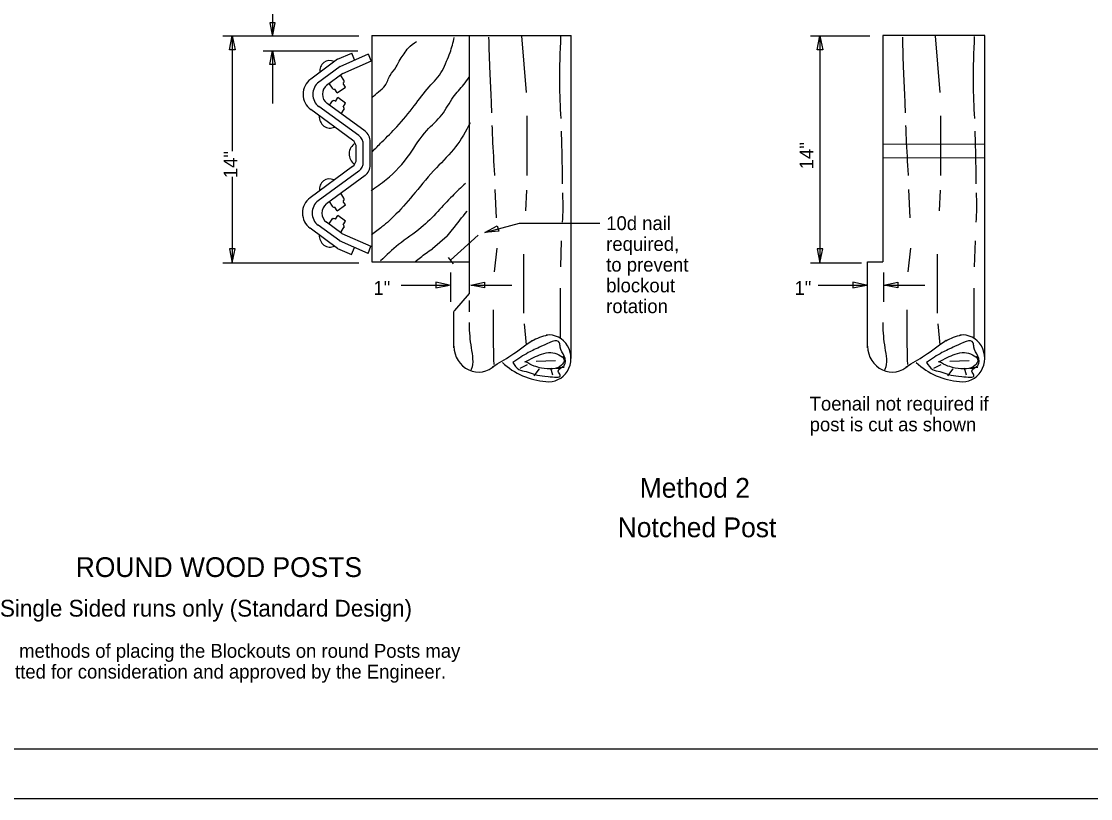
# Model space of a CAD drawing. Extents: x 0 to 34, y 0 to 22.
# Drawn here: x 8.31 to 19.13, y 0 to 7.86 of the extents above; entities that cross this region are included whole.
import ezdxf

# ---------------------------------------------------------------- set-up
doc = ezdxf.new("R2010")
doc.units = 0
for name, color, linetype in [('SH_Border', 7, 'Continuous'), ('SH_Cut_Line', 7, 'Continuous'), ('ST_Details', 7, 'Continuous'), ('ST_Text', 7, 'Continuous')]:
    doc.layers.add(name, color=color, linetype=linetype)

msp = doc.modelspace()

# ---------------------------------------------------------------- linework, layer by layer
at = {"layer": 'SH_Border'}
msp.add_lwpolyline([(1.5, 21.5), (33.5, 21.5), (33.5, 0.5), (1.5, 0.5)], close=True, dxfattribs=at)
at = {"layer": 'SH_Cut_Line'}
msp.add_lwpolyline([(0, 0), (34, 0), (34, 22), (0, 22)], close=True, dxfattribs=at)
at = {"layer": 'ST_Details'}
for p, q in [((11.853447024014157, 7.720612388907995), (11.853447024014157, 5.430445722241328)), ((11.853447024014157, 7.720612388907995), (13.87353035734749, 7.720445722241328)), ((12.839697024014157, 7.720612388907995), (12.839697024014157, 5.1087790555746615)), ((13.369697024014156, 7.7146123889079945), (13.416863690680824, 7.141945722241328)), ((13.87353035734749, 4.453612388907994), (13.87353035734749, 7.720445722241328)), ((17.026280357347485, 7.720612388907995), (17.026280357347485, 5.430445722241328)), ((18.06011369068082, 7.720445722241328), (17.026280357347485, 7.720612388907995)), ((17.556280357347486, 7.7146123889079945), (17.60344702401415, 7.141945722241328)), ((18.06011369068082, 4.453612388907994), (18.06011369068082, 7.720445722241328)), ((11.508863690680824, 7.478612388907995), (11.235947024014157, 7.278779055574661)), ((11.508613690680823, 7.4791123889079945), (11.65253035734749, 7.541779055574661)), ((11.533363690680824, 7.406112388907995), (11.82278035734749, 7.532445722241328)), ((11.68003035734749, 7.471779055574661), (11.652947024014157, 7.541112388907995)), ((11.848947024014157, 7.462112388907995), (11.821947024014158, 7.531445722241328)), ((11.535863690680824, 7.407445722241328), (11.305863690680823, 7.238945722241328)), ((11.562530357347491, 7.335445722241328), (11.852030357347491, 7.461779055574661)), ((11.561697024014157, 7.335112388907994), (11.394947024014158, 7.212945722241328)), ((11.572363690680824, 7.268279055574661), (11.542197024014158, 7.3156123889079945)), ((11.456530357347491, 7.1857790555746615), (11.427447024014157, 7.231445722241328)), ((11.505280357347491, 7.1392790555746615), (11.482113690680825, 7.175612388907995)), ((11.505113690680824, 7.139779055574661), (11.587613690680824, 7.198279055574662)), ((11.587530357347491, 7.198279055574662), (11.564863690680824, 7.2337790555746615)), ((11.426863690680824, 7.013112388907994), (11.458613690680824, 7.063112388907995)), ((11.486863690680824, 7.053445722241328), (11.51153035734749, 7.092112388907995)), ((11.59003035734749, 7.034445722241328), (11.511363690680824, 7.091945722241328)), ((11.56578035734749, 6.995945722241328), (11.589697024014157, 7.0336123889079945)), ((11.65953035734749, 6.661779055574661), (11.236280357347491, 6.970112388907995)), ((11.722697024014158, 6.706779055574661), (11.31878035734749, 7.001112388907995)), ((11.785863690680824, 6.751779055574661), (11.401197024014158, 7.032112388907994)), ((11.544947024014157, 6.927112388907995), (11.575947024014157, 6.975612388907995)), ((13.42428035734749, 6.908445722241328), (13.42428035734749, 6.303779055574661)), ((17.61086369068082, 6.908445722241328), (17.61086369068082, 6.303779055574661)), ((11.768697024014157, 6.440779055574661), (11.768697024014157, 6.614112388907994)), ((11.83953035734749, 6.411279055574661), (11.83953035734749, 6.643779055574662)), ((17.026280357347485, 6.621529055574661), (18.061197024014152, 6.6247790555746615)), ((11.697863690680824, 6.470279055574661), (11.697863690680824, 6.584612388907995)), ((11.768697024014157, 6.522112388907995), (11.768697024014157, 6.532945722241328)), ((11.659697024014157, 6.393112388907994), (11.229363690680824, 6.077612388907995)), ((17.026280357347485, 6.480695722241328), (18.060613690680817, 6.4839457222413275)), ((11.722863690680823, 6.348279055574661), (11.31178035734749, 6.046945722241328)), ((11.786113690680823, 6.303279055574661), (11.394447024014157, 6.016112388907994)), ((11.572363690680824, 6.075612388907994), (11.542197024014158, 6.122945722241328)), ((13.100697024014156, 6.161779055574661), (13.11303035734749, 5.874279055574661)), ((13.419363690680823, 6.154112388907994), (13.410197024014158, 5.944779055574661)), ((17.287280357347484, 6.161779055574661), (17.299613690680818, 5.874279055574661)), ((17.605947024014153, 6.154112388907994), (17.596780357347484, 5.944779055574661)), ((11.456530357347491, 5.992945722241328), (11.427447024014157, 6.038612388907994)), ((11.505280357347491, 5.946612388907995), (11.482113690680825, 5.982945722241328)), ((11.505113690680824, 5.946945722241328), (11.587613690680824, 6.005612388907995)), ((11.587530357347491, 6.005445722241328), (11.564863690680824, 6.040945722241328)), ((11.426863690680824, 5.8204457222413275), (11.458613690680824, 5.870445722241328)), ((11.486863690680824, 5.860779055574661), (11.51153035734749, 5.899445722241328)), ((11.59003035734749, 5.841779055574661), (11.511363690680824, 5.899279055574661)), ((11.509113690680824, 5.565279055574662), (11.229697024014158, 5.7691123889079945)), ((11.529947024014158, 5.641279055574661), (11.312113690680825, 5.799945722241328)), ((11.55203035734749, 5.716279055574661), (11.394613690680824, 5.830945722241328)), ((11.544947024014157, 5.734279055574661), (11.575947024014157, 5.782945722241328)), ((11.56578035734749, 5.803279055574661), (11.589697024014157, 5.840779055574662)), ((11.817780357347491, 5.515612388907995), (11.528363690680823, 5.641779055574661)), ((11.55203035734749, 5.716779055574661), (11.845697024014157, 5.588612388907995)), ((12.250947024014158, 5.694945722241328), (12.250947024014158, 5.694945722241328)), ((12.615780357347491, 5.689945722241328), (12.467863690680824, 5.562445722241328)), ((12.650197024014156, 5.4452790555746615), (12.930613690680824, 5.698945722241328)), ((13.772447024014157, 5.643445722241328), (13.76478035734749, 5.378279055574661)), ((17.959030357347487, 5.643445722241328), (17.951363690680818, 5.378279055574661)), ((11.506863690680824, 5.566279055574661), (11.650780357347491, 5.503445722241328)), ((11.649947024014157, 5.503779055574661), (11.678280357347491, 5.576279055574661)), ((11.816947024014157, 5.515612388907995), (11.845613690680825, 5.589112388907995)), ((13.118947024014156, 5.569279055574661), (13.093613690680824, 5.327112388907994)), ((17.305530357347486, 5.569279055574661), (17.280197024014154, 5.327112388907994)), ((11.853447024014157, 5.430445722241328), (12.84503035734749, 5.430445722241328)), ((12.68153035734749, 5.410945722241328), (12.630613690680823, 5.472112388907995)), ((13.390697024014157, 5.507112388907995), (13.390697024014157, 4.909612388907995)), ((16.871780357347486, 4.6392790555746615), (16.871780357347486, 5.430445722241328)), ((16.871780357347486, 5.430445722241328), (17.026280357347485, 5.430445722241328)), ((17.577280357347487, 5.507112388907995), (17.577280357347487, 4.909612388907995)), ((12.839697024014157, 5.1087790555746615), (12.691947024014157, 4.938112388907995)), ((12.839697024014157, 5.037612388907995), (12.839697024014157, 4.923779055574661)), ((12.685197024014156, 4.6392790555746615), (12.685197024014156, 4.9261123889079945)), ((12.691947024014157, 4.9309457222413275), (12.691947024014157, 4.938112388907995)), ((13.397863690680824, 4.803612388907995), (13.417613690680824, 4.589445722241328)), ((17.584447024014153, 4.803612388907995), (17.60419702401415, 4.589445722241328)), ((12.685197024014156, 4.560945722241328), (12.685197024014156, 4.6392790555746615)), ((16.871780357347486, 4.560945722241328), (16.871780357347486, 4.6392790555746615)), ((13.80053035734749, 4.440112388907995), (13.794613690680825, 4.474779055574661)), ((17.987113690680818, 4.440112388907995), (17.98119702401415, 4.474779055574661)), ((13.35703035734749, 4.354779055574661), (13.43103035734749, 4.390279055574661)), ((13.498113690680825, 4.276445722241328), (13.551947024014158, 4.3476123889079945)), ((13.518363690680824, 4.425779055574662), (13.713197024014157, 4.432945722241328)), ((13.68628035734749, 4.2836123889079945), (13.666113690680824, 4.354779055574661)), ((13.80128035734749, 4.361112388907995), (13.720613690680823, 4.353945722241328)), ((13.720613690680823, 4.353945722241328), (13.760197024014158, 4.354779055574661)), ((17.543613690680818, 4.354779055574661), (17.61761369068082, 4.390279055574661)), ((17.684697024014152, 4.276445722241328), (17.738530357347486, 4.3476123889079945)), ((17.704947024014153, 4.425779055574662), (17.899780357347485, 4.432945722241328)), ((17.87286369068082, 4.2836123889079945), (17.85269702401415, 4.354779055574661)), ((17.98786369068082, 4.361112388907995), (17.907197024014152, 4.353945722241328)), ((17.907197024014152, 4.353945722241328), (17.946780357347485, 4.354779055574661))]:
    msp.add_line(p, q, dxfattribs=at)
for centre, major_axis, ratio, start_param, end_param in [((11.428547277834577, 7.35975966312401), (-1.7132284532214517e-17, -0.10653593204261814), 0.9445438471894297, 2.6872111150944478, 4.851440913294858), ((11.336730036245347, 7.1245756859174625), (-3.014770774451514e-17, -0.18747144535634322), 0.9445438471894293, 3.7470844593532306, 5.680264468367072), ((11.556454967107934, 7.255854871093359), (1.2145060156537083e-18, 0.019834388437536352), 0.9445438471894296, 3.7043701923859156, 5.352473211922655), ((11.399075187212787, 7.124683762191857), (-2.4118166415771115e-17, -0.14997715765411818), 0.9445438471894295, 3.7471373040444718, 5.680323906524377), ((11.46144141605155, 7.124774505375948), (-1.8088624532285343e-17, -0.11248286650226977), 0.9445438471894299, 3.747102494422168, 5.680297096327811), ((11.469404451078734, 7.196378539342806), (-3.142739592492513e-18, -0.01954290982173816), 0.9445438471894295, 5.247458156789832, 6.879591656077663), ((11.471088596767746, 7.039917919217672), (1.2880049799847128e-18, 0.021034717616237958), 0.9445438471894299, 5.4523006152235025, 7.118325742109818), ((11.556745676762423, 6.977427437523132), (1.2880049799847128e-18, 0.021034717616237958), 0.9445438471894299, 4.196406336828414, 5.735380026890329), ((11.431739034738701, 6.897239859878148), (-1.8497404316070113e-17, -0.11502483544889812), 0.9445438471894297, 4.64065114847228, 6.714316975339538), ((11.715549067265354, 6.643707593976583), (8.035522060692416e-18, 0.13123003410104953), 0.9445438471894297, 4.71238898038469, 5.680267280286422), ((11.738150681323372, 6.521138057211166), (-1.929587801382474e-17, -0.11999008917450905), 0.9445438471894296, 3.613765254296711, 5.741419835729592), ((11.609304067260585, 6.584565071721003), (5.739657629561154e-18, 0.09373572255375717), 0.9445438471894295, 4.71238898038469, 5.68037747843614), ((11.662426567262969, 6.6141456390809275), (6.8875891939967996e-18, 0.11248286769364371), 0.9445438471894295, 4.71238898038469, 5.680339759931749), ((11.609304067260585, 6.470209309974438), (-1.5073853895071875e-17, -0.09373572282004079), 0.9445438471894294, 0.6055627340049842, 1.5707963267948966), ((11.662426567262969, 6.440778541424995), (-1.8088624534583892e-17, -0.11248286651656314), 0.9445438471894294, 0.6056505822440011, 1.5707963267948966), ((11.715549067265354, 6.411198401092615), (-2.110339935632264e-17, -0.13123003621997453), 0.9445438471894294, 0.6055663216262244, 1.5707963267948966), ((11.425525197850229, 6.162841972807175), (-1.7132284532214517e-17, -0.10653593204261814), 0.9445438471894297, 2.6872111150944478, 4.851440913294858), ((11.33010480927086, 5.923497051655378), (-3.0147707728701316e-17, -0.18747144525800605), 0.9445438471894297, 3.7470910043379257, 5.6802800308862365), ((11.556454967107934, 6.06313654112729), (1.2145060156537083e-18, 0.019834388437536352), 0.9445438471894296, 3.7043701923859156, 5.352473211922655), ((11.392427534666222, 5.923610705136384), (-2.4118166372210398e-17, -0.14997715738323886), 0.9445438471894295, 3.7471148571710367, 5.680354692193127), ((11.454839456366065, 5.923718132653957), (-1.8088624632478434e-17, -0.11248286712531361), 0.9445438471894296, 3.747102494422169, 5.680258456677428), ((11.469404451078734, 6.003660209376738), (-3.142739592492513e-18, -0.01954290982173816), 0.9445438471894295, 5.247458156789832, 6.879591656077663), ((11.471088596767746, 5.847199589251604), (1.2880049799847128e-18, 0.021034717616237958), 0.9445438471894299, 5.4523006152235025, 7.118325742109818), ((11.556745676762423, 5.7847091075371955), (1.2880049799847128e-18, 0.021034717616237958), 0.9445438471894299, 4.196406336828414, 5.735380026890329), ((11.431739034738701, 5.693923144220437), (-1.8497404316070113e-17, -0.11502483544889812), 0.9445438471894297, 4.64065114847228, 6.714316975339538), ((13.718377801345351, 4.187549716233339), (3.1110609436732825e-17, 0.5080748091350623), 0.9445438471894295, 0.17943739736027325, 0.5303528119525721), ((13.646788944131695, 4.453758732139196), (1.4492221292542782e-17, 0.23667593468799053), 0.9445438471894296, 2.997306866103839, 6.4059503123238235), ((17.90496113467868, 4.187549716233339), (3.1110609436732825e-17, 0.5080748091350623), 0.9445438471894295, 0.17943739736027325, 0.5303528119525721), ((17.833372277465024, 4.453758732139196), (1.4492221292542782e-17, 0.23667593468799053), 0.9445438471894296, 2.997306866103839, 6.4059503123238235), ((12.934531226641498, 4.578969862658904), (-4.245406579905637e-17, -0.2639976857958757), 0.9445438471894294, 4.7265868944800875, 7.018322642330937), ((17.121114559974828, 4.578969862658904), (-4.245406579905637e-17, -0.2639976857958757), 0.9445438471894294, 4.7265868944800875, 7.018322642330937), ((13.660946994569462, 4.998499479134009), (-1.254338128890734e-16, -0.7800015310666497), 0.9445438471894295, 5.5640474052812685, 6.222034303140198), ((17.847530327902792, 4.998499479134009), (-1.254338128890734e-16, -0.7800015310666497), 0.9445438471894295, 5.5640474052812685, 6.222034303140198)]:
    msp.add_ellipse(centre, major_axis=major_axis, ratio=ratio, start_param=start_param, end_param=end_param, dxfattribs=at)
for points in [[(11.858363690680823, 6.543279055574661), (11.956530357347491, 6.643279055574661), (12.109113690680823, 6.797112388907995), (12.283447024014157, 7.008612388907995), (12.43603035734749, 7.200945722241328), (12.56678035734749, 7.362445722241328), (12.610363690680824, 7.458612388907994), (12.64678035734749, 7.547112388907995), (12.689197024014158, 7.699779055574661)], [(13.037197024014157, 7.702112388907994), (13.048030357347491, 7.349445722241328), (13.061447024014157, 7.064945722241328), (13.065863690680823, 6.9374457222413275)], [(13.765113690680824, 7.7099457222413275), (13.75353035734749, 7.242779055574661), (13.765947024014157, 6.880112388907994)], [(17.223780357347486, 7.702112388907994), (17.23461369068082, 7.349445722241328), (17.248030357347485, 7.064945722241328), (17.252447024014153, 6.9374457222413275)], [(17.951697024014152, 7.7099457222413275), (17.940113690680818, 7.242779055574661), (17.952530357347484, 6.880112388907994)], [(11.85478035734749, 7.089445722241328), (11.923863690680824, 7.150945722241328), (11.989197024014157, 7.212445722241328), (12.040113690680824, 7.316279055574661), (12.101863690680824, 7.400945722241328), (12.141780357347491, 7.477945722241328), (12.18178035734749, 7.535612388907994), (12.225363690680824, 7.593279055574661), (12.30828035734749, 7.659279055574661)], [(11.847530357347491, 6.150945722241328), (12.000113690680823, 6.262445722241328), (12.239863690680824, 6.520279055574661), (12.41053035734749, 6.758612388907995), (12.563197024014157, 6.916445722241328), (12.679447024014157, 7.097112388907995), (12.784863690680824, 7.223945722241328), (12.840363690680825, 7.298279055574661)], [(12.85103035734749, 6.835445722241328), (12.70328035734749, 6.593612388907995), (12.508447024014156, 6.380112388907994), (12.293363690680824, 6.131112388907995), (12.09853035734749, 5.910779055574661), (11.957447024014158, 5.782612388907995), (11.849863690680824, 5.704279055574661)], [(13.070363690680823, 6.809445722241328), (13.074863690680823, 6.6809457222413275), (13.09503035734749, 6.310945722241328), (13.095363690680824, 6.304112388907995)], [(13.770447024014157, 6.752112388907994), (13.773613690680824, 6.659445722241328), (13.782197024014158, 6.218779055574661)], [(17.256947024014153, 6.809445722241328), (17.261447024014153, 6.6809457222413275), (17.281613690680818, 6.310945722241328), (17.28194702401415, 6.304112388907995)], [(17.957030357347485, 6.752112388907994), (17.960197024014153, 6.659445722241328), (17.968780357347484, 6.218779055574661)], [(12.804030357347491, 6.223612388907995), (12.669613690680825, 6.095612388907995), (12.52178035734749, 5.939112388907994), (12.35378035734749, 5.775612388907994), (12.125363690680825, 5.604779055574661), (11.94403035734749, 5.439612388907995)], [(13.78403035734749, 6.1264457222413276), (13.787113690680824, 5.9694457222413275), (13.78228035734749, 5.832279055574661)], [(17.970613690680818, 6.1264457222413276), (17.973697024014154, 5.9694457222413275), (17.96886369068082, 5.832279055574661)], [(12.615780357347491, 5.689945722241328), (12.672197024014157, 5.758612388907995), (12.818197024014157, 5.943279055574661)], [(12.29428035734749, 5.431612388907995), (12.40328035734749, 5.516445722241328), (12.467863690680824, 5.562445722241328)], [(13.760947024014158, 5.1647790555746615), (13.760947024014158, 4.951445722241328), (13.760947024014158, 4.702445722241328), (13.760947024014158, 4.659779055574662)], [(17.947530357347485, 5.1647790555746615), (17.947530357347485, 4.951445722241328), (17.947530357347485, 4.702445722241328), (17.947530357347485, 4.659779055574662)], [(13.081530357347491, 4.945112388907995), (13.081530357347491, 4.774445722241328), (13.088280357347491, 4.390279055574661)], [(17.268113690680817, 4.945112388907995), (17.268113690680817, 4.774445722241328), (17.274863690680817, 4.390279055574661)], [(12.839697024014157, 4.8171123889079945), (12.839697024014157, 4.795779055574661), (12.859780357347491, 4.560945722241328), (12.859780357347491, 4.340445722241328), (12.853113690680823, 4.326279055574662)], [(17.026280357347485, 4.8171123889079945), (17.026280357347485, 4.795779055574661), (17.04636369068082, 4.560945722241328), (17.04636369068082, 4.340445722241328), (17.039697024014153, 4.326279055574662)], [(13.283197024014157, 4.411612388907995), (13.437697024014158, 4.511279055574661), (13.572113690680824, 4.575279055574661), (13.75353035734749, 4.610779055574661), (13.760947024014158, 4.567279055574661), (13.80128035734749, 4.474779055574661), (13.80128035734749, 4.382445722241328), (13.740863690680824, 4.325445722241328), (13.760197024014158, 4.2836123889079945), (13.639197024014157, 4.269445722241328), (13.53178035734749, 4.2836123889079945), (13.417613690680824, 4.319112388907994), (13.343613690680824, 4.340445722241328), (13.283197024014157, 4.411612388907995)], [(17.469780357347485, 4.411612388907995), (17.624280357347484, 4.511279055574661), (17.75869702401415, 4.575279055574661), (17.940113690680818, 4.610779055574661), (17.947530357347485, 4.567279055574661), (17.98786369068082, 4.474779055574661), (17.98786369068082, 4.382445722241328), (17.927447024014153, 4.325445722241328), (17.946780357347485, 4.2836123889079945), (17.825780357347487, 4.269445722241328), (17.718363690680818, 4.2836123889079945), (17.60419702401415, 4.319112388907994), (17.530197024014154, 4.340445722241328), (17.469780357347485, 4.411612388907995)], [(13.074863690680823, 4.368945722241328), (13.262947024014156, 4.482779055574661), (13.481197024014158, 4.638945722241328)], [(17.261447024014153, 4.368945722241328), (17.449530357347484, 4.482779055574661), (17.667780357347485, 4.638945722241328)], [(13.404113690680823, 4.418779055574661), (13.491447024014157, 4.461445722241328), (13.572113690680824, 4.497112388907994), (13.666113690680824, 4.511279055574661), (13.74678035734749, 4.489945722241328), (13.80053035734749, 4.440112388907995), (13.773613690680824, 4.383112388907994), (13.68628035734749, 4.3476123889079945), (13.572113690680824, 4.354779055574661), (13.498113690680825, 4.376112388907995), (13.410780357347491, 4.418779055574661)], [(17.59069702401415, 4.418779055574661), (17.678030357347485, 4.461445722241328), (17.75869702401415, 4.497112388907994), (17.85269702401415, 4.511279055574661), (17.933363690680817, 4.489945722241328), (17.987113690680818, 4.440112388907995), (17.960197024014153, 4.383112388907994), (17.87286369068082, 4.3476123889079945), (17.75869702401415, 4.354779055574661), (17.684697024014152, 4.376112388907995), (17.59736369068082, 4.418779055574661)]]:
    msp.add_spline(points, degree=3, dxfattribs=at)
at = {"layer": 'ST_Text'}
for p, q in [((10.849113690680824, 8.36219289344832), (10.849113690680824, 7.708612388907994)), ((10.34853035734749, 7.715945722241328), (11.72278035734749, 7.715945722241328)), ((10.44303035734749, 7.715945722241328), (10.44303035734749, 6.549279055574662)), ((16.295780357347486, 7.715945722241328), (16.89561369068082, 7.715945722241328)), ((16.390280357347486, 7.715945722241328), (16.390280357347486, 6.549279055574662)), ((10.754697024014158, 7.565779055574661), (11.712197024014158, 7.565779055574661)), ((10.849113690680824, 7.565779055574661), (10.849113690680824, 7.0302790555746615)), ((16.390280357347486, 6.549279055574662), (16.390280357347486, 6.291112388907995)), ((10.44303035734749, 6.291112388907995), (10.44303035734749, 5.421445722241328)), ((16.390280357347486, 6.291112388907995), (16.390280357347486, 5.421445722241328)), ((12.997197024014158, 5.727112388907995), (13.347697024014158, 5.819779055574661)), ((13.347697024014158, 5.819779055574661), (14.161947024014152, 5.819779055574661)), ((10.34853035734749, 5.421445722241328), (11.447197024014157, 5.421445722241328)), ((11.447197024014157, 5.421445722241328), (11.72278035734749, 5.421445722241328)), ((16.295780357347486, 5.421445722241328), (16.620030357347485, 5.421445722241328)), ((16.620030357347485, 5.421445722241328), (16.809197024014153, 5.421445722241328)), ((12.649613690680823, 5.322779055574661), (12.649613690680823, 5.026112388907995)), ((17.032197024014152, 5.322779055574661), (17.032197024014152, 5.026112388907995)), ((12.15303035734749, 5.195445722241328), (12.642447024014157, 5.195445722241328)), ((12.855947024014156, 5.195445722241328), (13.27028035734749, 5.195445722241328)), ((16.37261369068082, 5.195445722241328), (16.862030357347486, 5.195445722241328)), ((17.03719702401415, 5.195445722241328), (17.451530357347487, 5.195445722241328))]:
    msp.add_line(p, q, dxfattribs=at)
for points in [[(10.821113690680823, 7.848612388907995), (10.849113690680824, 7.708612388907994), (10.877113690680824, 7.848612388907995)], [(10.41503035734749, 7.575945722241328), (10.44303035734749, 7.715945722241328), (10.471030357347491, 7.575945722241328)], [(16.362280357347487, 7.575945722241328), (16.390280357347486, 7.715945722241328), (16.418280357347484, 7.575945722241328)], [(10.821113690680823, 7.425779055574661), (10.849113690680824, 7.565779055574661), (10.877113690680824, 7.425779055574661)], [(13.139491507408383, 5.738786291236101), (12.997197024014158, 5.727112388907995), (13.124055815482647, 5.79261694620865)], [(10.41503035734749, 5.561445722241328), (10.44303035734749, 5.421445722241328), (10.471030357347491, 5.561445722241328)], [(16.362280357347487, 5.561445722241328), (16.390280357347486, 5.421445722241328), (16.418280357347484, 5.561445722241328)], [(12.502447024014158, 5.167445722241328), (12.642447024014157, 5.195445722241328), (12.502447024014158, 5.223445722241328)], [(12.995947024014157, 5.167445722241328), (12.855947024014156, 5.195445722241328), (12.995947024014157, 5.223445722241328)], [(16.722030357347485, 5.167445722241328), (16.862030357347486, 5.195445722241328), (16.722030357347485, 5.223445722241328)], [(17.177197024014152, 5.167445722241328), (17.03719702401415, 5.195445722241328), (17.177197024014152, 5.223445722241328)]]:
    msp.add_lwpolyline(points, close=True, dxfattribs=at)

# ---------------------------------------------------------------- texts
for p in [(16.323268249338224, 6.366505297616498), (10.494087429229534, 6.276050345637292)]:
    msp.add_text('14" ', height=0.13999972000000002, rotation=89.99999999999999, dxfattribs=at).set_placement(p)
for s, height, p in [('10d nail ', 0.13999972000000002, (14.226630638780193, 5.751182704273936)), ('required, ', 0.13999972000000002, (14.226630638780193, 5.541183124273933)), ('to prevent ', 0.13999972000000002, (14.226630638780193, 5.331183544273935)), ('1"', 0.13999972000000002, (11.871134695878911, 5.095761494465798)), ('blockout ', 0.13999972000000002, (14.226630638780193, 5.121183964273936)), ('1" ', 0.13999972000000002, (16.131998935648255, 5.095761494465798)), ('rotation', 0.13999972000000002, (14.226630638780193, 4.911184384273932)), ('Toenail not required if', 0.13999972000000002, (16.28573067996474, 3.9252995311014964)), ('post is cut as shown', 0.13999972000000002, (16.28573067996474, 3.715299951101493)), ('   Method 2', 0.19999960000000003, (14.342963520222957, 3.0439502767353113)), ('Notched Post', 0.19999960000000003, (14.342963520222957, 2.6439510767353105)), ('ROUND WOOD POSTS', 0.19999960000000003, (8.858601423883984, 2.241601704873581)), ('Single Sided runs only (Standard Design)', 0.16999966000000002, (8.091368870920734, 1.840897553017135)), ('Alternate methods of placing the Blockouts on round Posts may', 0.13999972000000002, (7.484544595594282, 1.4246651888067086)), ('be submitted for consideration and approved by the Engineer.', 0.13999972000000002, (7.484544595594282, 1.2146656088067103))]:
    msp.add_text(s, height=height, dxfattribs=at).set_placement(p)

doc.saveas('drawing.dxf')
